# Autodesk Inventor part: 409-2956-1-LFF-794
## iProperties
Created: 2010-11
Part Number: 409-2956-1-LFF-794
Cost Center: 0 lbmass
Material: A304 STAINLESS STEEL
Document SubType Name: Sheet Metal
Designer: S. Boerckel
Authority: 0 in^3
Mass: 794.445 g
Surface Area: 357.51 cm^2
Volume: 98.3224 cm^3
Density: 8.08 g/cm^3
Flat Pattern Width: 5.08 cm
Flat Pattern Length: 35.56 cm
Flat Pattern Area: 180.645 cm^2
Sheet Metal Rule: 1/4"Thk
Description: 2" PIPE ANGLE SUPPORT
SaveDate: 2008-01-15
SaveTime: 10:24
FileName: Sheet Metal
Wide: =<Flat Pattern Width>cm
Length: =<Flat Pattern Length>cm
Thickness: 0.2500 in
SMR: =<Sheet Metal Rule> - <Material>
Author: S. Boerckel
Revision Number: 0
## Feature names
1. Plate1
